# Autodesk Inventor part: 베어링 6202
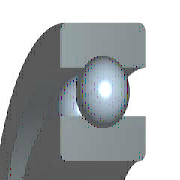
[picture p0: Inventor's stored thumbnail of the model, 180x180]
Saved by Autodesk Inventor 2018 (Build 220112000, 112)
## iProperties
IsCustomPart: 1
Created: 2015-09
Part Number: 베어링 6202
Material: 강철, 연강
Description: 깊은 그루브 볼 베어링
Document SubType Name: Modeling
Standard: KS B 2023
Designer: mduedu
Standards Organization: KS
Language: ko-KR
Size Designation: 6202 - 15 x 35 x 11
Categories: <MemberInstance><Categories><Category DisplayName="샤프트 부품" InternalName="7f7aeb1f-a693-4053-b835-cee3144e0d98" Mnemonic="SHFT"><Category DisplayName="베어링" Inter
Density: 7.86 g/cm^3
Mass: 45.8725 g
Surface Area: 51.5584 cm^2
Volume: 5.83619 cm^3
Appearance: 노란색
Author: mduedu
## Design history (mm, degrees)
sketch "스케치" dims "d0" = 5.2 (= -0.26 x WD + 0.26 x BD)
  geometry: L1 (2.9, 12.5)-(8.1, 12.5); L2 (5.5, 12.5)-(5.5, 9.9); L3 (5.5, 12.5)-(5.5, 15.1); L4 (3.568, 10.76)-(0, 10.76); L5 (0, 7.5)-(11, 7.5); L6 (3.568, 14.24)-(0, 14.24); L7 (0, 17.5)-(11, 17.5); L8 (11, 7.5)-(11, 10.76); L9 (7.432, 10.76)-(11, 10.76); L10 (7.432, 14.24)-(11, 14.24); L11 (11, 17.5)-(11, 14.24); L12 (-1.4, 0)-(8.4, 0) reference; L13 (0, -0.3)-(0, 5.3) reference
  constraints: 22 end point, 4 point on line, 2 collinear, 2 perpendicular, 2 symmetric about line, 1 midpoint, 1 parallel, 14 other
  dimensions: "d9" = 15 diameter of L5 L12 (= WD); "d11" = 35 diameter of L7 L12 (= BD); "d12" = 11 distance between parallel lines of L8 L13 (= KB); "d13" = 21.52 diameter of L9 L12 (= 0.326 x BD + 0.674 x WD)
revolve "본체" stored, may be unused: angle "d6" = 90 deg
revolve "볼" stored, may be unused: angle "d7" = 90 deg
pattern_circular "IDS_ARRAYBALL[SIMPL:T]" dims angle "d3" = 360 deg
body "Solid1"
fillet "모깎기1" dims "d1" = 0.6 (= KRS)
other parameters: "WD" = 15 [user parameter; used in 5 equation terms], "BD" = 35 [user parameter; used in 5 equation terms], "KB" = 11 [user parameter; used in 1 equation term], "KRS" = 0.6 [user parameter; used in 1 equation term], "d4" = 0, "d5" = 0, "d8" = 0, "d14" = 0, "d15" = 0, "BBA" = 0 [user parameter], "BC0" = 3750000 [user parameter], "BC" = 7800000 [user parameter], "BR" = 17.5 (= 0.5 x BD) [user parameter], "WR" = 7.5 (= 0.5 x WD) [user parameter]
